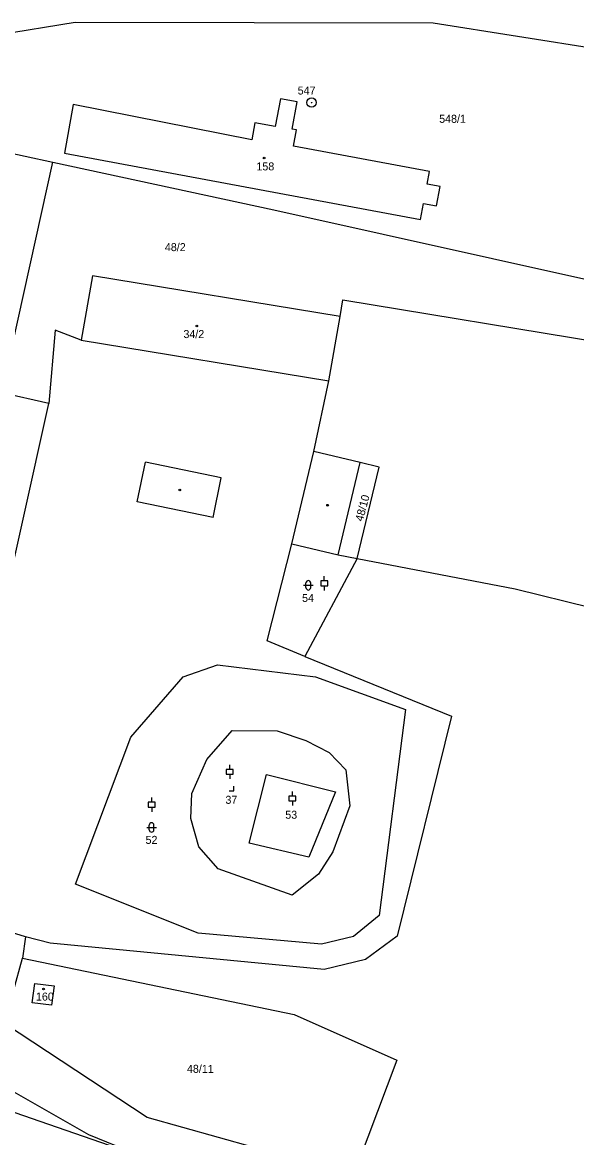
# Model space of a CAD drawing. Extents: x -801826 to -800592, y -1032871 to -1031813.
# Drawn here: x -801242.3 to -801124.4, y -1032295.9 to -1032058.9 of the extents above; entities that cross this region are included whole.
import ezdxf

# ---------------------------------------------------------------- set-up
doc = ezdxf.new("R2010")
doc.units = 0
for name, color, linetype in [('Vrstva 1', 7, 'Continuous'), ('Vrstva 17', 7, 'Continuous'), ('Vrstva 18', 7, 'Continuous'), ('Vrstva 19', 7, 'Continuous'), ('Vrstva 24', 7, 'Continuous'), ('Vrstva 25', 7, 'Continuous'), ('Vrstva 4', 7, 'Continuous')]:
    doc.layers.add(name, color=color, linetype=linetype)

msp = doc.modelspace()

# ---------------------------------------------------------------- linework, layer by layer
at = {"layer": 'Vrstva 1'}
for p, q in [((-801262.98, -1032064), (-801231.11, -1032058.94)), ((-801231.11, -1032058.94), (-801155, -1032059.05)), ((-801155, -1032059.05), (-801101, -1032067.63)), ((-801231.51, -1032076.39), (-801233.35, -1032086.76)), ((-801193.55, -1032083.9), (-801231.51, -1032076.39)), ((-801187.45, -1032075.17), (-801188.55, -1032081.07)), ((-801183.86, -1032075.84), (-801187.45, -1032075.17)), ((-801184.94, -1032081.64), (-801183.86, -1032075.84)), ((-801192.87, -1032080.26), (-801193.55, -1032083.9)), ((-801188.55, -1032081.07), (-801192.87, -1032080.26)), ((-801258.71, -1032083.73), (-801235.82, -1032088.67)), ((-801184.01, -1032081.81), (-801184.94, -1032081.64)), ((-801184.65, -1032085.25), (-801184.01, -1032081.81)), ((-801155.75, -1032090.64), (-801184.65, -1032085.25)), ((-801245.62, -1032132.9), (-801235.82, -1032088.67)), ((-801235.82, -1032088.67), (-801188.88, -1032098.79)), ((-801233.35, -1032086.76), (-801157.65, -1032100.86)), ((-801156.24, -1032093.29), (-801155.75, -1032090.64)), ((-801153.49, -1032093.8), (-801156.24, -1032093.29)), ((-801154.26, -1032097.93), (-801153.49, -1032093.8)), ((-801157.65, -1032100.86), (-801157.01, -1032097.42)), ((-801157.01, -1032097.42), (-801154.26, -1032097.93)), ((-801188.88, -1032098.79), (-801114.92, -1032115.22)), ((-801227.44, -1032112.79), (-801229.85, -1032126.45)), ((-801174.76, -1032121.41), (-801227.44, -1032112.79)), ((-801174.76, -1032121.41), (-801174.17, -1032117.88)), ((-801174.17, -1032117.88), (-801118.72, -1032127.06)), ((-801177.15, -1032135.08), (-801174.76, -1032121.41)), ((-801235.38, -1032124.35), (-801236.7, -1032139.95)), ((-801229.85, -1032126.45), (-801235.38, -1032124.35)), ((-801229.85, -1032126.45), (-801177.15, -1032135.08)), ((-801180.36, -1032150.13), (-801177.15, -1032135.08)), ((-801236.7, -1032139.95), (-801246.67, -1032137.64)), ((-801170.51, -1032152.42), (-801180.36, -1032150.13)), ((-801175.17, -1032172.07), (-801170.51, -1032152.42)), ((-801166.45, -1032153.44), (-801170.51, -1032152.42)), ((-801171.1, -1032172.83), (-801166.45, -1032153.44)), ((-801190.26, -1032190.37), (-801185.04, -1032169.71)), ((-801185.04, -1032169.71), (-801175.17, -1032172.07)), ((-801171.1, -1032172.83), (-801182.26, -1032193.66)), ((-801175.17, -1032172.07), (-801171.1, -1032172.83)), ((-801171.1, -1032172.83), (-801137.55, -1032179.29)), ((-801137.55, -1032179.29), (-801121.44, -1032183.28)), ((-801182.26, -1032193.66), (-801190.26, -1032190.37)), ((-801182.26, -1032193.66), (-801151.09, -1032206.33)), ((-801208.1, -1032197.96), (-801200.82, -1032195.46)), ((-801200.82, -1032195.46), (-801180, -1032197.96)), ((-801219.29, -1032210.8), (-801208.1, -1032197.96)), ((-801180, -1032197.96), (-801160.86, -1032204.93)), ((-801160.86, -1032204.93), (-801166.44, -1032248.68)), ((-801151.09, -1032206.33), (-801162.63, -1032253.04)), ((-801203.12, -1032215.52), (-801197.7, -1032209.41)), ((-801197.7, -1032209.41), (-801188.12, -1032209.45)), ((-801188.12, -1032209.45), (-801182.05, -1032211.53)), ((-801231.06, -1032242.05), (-801219.29, -1032210.8)), ((-801182.05, -1032211.53), (-801177.08, -1032214.05)), ((-801177.08, -1032214.05), (-801173.53, -1032217.76)), ((-801206.3, -1032222.74), (-801203.12, -1032215.52)), ((-801194.07, -1032233.33), (-801190.44, -1032218.75)), ((-801190.44, -1032218.75), (-801175.71, -1032222.38)), ((-801173.53, -1032217.76), (-801172.72, -1032225.39)), ((-801206.5, -1032228.08), (-801206.3, -1032222.74)), ((-801175.71, -1032222.38), (-801181.43, -1032236.27)), ((-801172.72, -1032225.39), (-801176.34, -1032235.17)), ((-801204.79, -1032234.11), (-801206.5, -1032228.08)), ((-801200.67, -1032238.8), (-801204.79, -1032234.11)), ((-801181.43, -1032236.27), (-801194.07, -1032233.33)), ((-801176.34, -1032235.17), (-801179.36, -1032239.9)), ((-801184.94, -1032244.39), (-801200.67, -1032238.8)), ((-801179.36, -1032239.9), (-801184.94, -1032244.39)), ((-801204.96, -1032252.47), (-801231.06, -1032242.05)), ((-801166.44, -1032248.68), (-801171.94, -1032253.12)), ((-801241.66, -1032253.23), (-801246.69, -1032251.67)), ((-801241.66, -1032253.23), (-801242.31, -1032257.72)), ((-801236.4, -1032254.58), (-801241.66, -1032253.23)), ((-801178.71, -1032254.75), (-801204.96, -1032252.47)), ((-801171.94, -1032253.12), (-801178.71, -1032254.75)), ((-801162.63, -1032253.04), (-801169.36, -1032258.05)), ((-801178.12, -1032260.13), (-801236.4, -1032254.58)), ((-801246.16, -1032271.65), (-801242.31, -1032257.72)), ((-801242.31, -1032257.72), (-801184.54, -1032269.72)), ((-801169.36, -1032258.05), (-801178.12, -1032260.13)), ((-801240.22, -1032267.23), (-801239.7, -1032263.13)), ((-801239.7, -1032263.13), (-801235.6, -1032263.65)), ((-801235.6, -1032263.65), (-801236.12, -1032267.75)), ((-801236.12, -1032267.75), (-801240.22, -1032267.23)), ((-801184.54, -1032269.72), (-801162.68, -1032279.42)), ((-801215.82, -1032291.6), (-801246.16, -1032271.65)), ((-801162.68, -1032279.42), (-801172.28, -1032304.86)), ((-801228.18, -1032295.28), (-801246.04, -1032285.11)), ((-801253.19, -1032287.31), (-801216.74, -1032299.98)), ((-801185.47, -1032300.06), (-801215.82, -1032291.6)), ((-801216.74, -1032299.98), (-801228.18, -1032295.28))]:
    msp.add_line(p, q, dxfattribs=at)
at = {"layer": 'Vrstva 24'}
for radius in [1, 0.0439]:
    msp.add_circle((-801180.84, -1032076), radius, dxfattribs=at)
at = {"layer": 'Vrstva 25'}
for p, q in [((-801182.52, -1032178.54), (-801180.52, -1032178.54)), ((-801182.02, -1032179.04), (-801182.02, -1032178.04)), ((-801181.02, -1032179.04), (-801181.02, -1032178.04)), ((-801178.14, -1032177.62), (-801178.14, -1032176.62)), ((-801178.14, -1032178.62), (-801178.14, -1032179.62)), ((-801198.24, -1032217.65), (-801198.24, -1032216.65)), ((-801198.24, -1032218.65), (-801198.24, -1032219.65)), ((-801197.33, -1032222.22), (-801197.33, -1032221.22)), ((-801214.83, -1032224.64), (-801214.83, -1032223.64)), ((-801198.33, -1032222.22), (-801197.33, -1032222.22)), ((-801184.91, -1032223.33), (-801184.91, -1032222.33)), ((-801214.83, -1032225.64), (-801214.83, -1032226.64)), ((-801184.91, -1032224.33), (-801184.91, -1032225.33)), ((-801215.84, -1032229.98), (-801213.84, -1032229.98)), ((-801215.34, -1032230.48), (-801215.34, -1032229.48)), ((-801214.34, -1032230.48), (-801214.34, -1032229.48))]:
    msp.add_line(p, q, dxfattribs=at)
for points in [[(-801178.89, -1032178.62), (-801177.39, -1032178.62), (-801177.39, -1032177.62), (-801178.89, -1032177.62)], [(-801198.99, -1032218.65), (-801197.49, -1032218.65), (-801197.49, -1032217.65), (-801198.99, -1032217.65)], [(-801185.66, -1032224.33), (-801184.16, -1032224.33), (-801184.16, -1032223.33), (-801185.66, -1032223.33)], [(-801215.58, -1032225.64), (-801214.08, -1032225.64), (-801214.08, -1032224.64), (-801215.58, -1032224.64)]]:
    msp.add_lwpolyline(points, close=True, dxfattribs=at)
for centre in [(-801190.92, -1032087.77), (-801205.23, -1032123.47), (-801208.86, -1032158.28), (-801177.43, -1032161.52), (-801237.82, -1032264.31)]:
    msp.add_circle(centre, 0.175, dxfattribs=at)
for centre, start, end in [((-801181.52, -1032178.04), 0, 180), ((-801181.52, -1032179.04), 180, 0), ((-801214.84, -1032229.48), 0, 180), ((-801214.84, -1032230.48), 180, 0)]:
    msp.add_arc(centre, 0.5, start, end, dxfattribs=at)
at = {"layer": 'Vrstva 4'}
for p, q in [((-801251.33, -1032205.54), (-801236.7, -1032139.95)), ((-801185.04, -1032169.71), (-801180.36, -1032150.13)), ((-801217.92, -1032160.79), (-801216.16, -1032152.37)), ((-801200.02, -1032155.74), (-801216.16, -1032152.37)), ((-801201.78, -1032164.16), (-801200.02, -1032155.74)), ((-801201.78, -1032164.16), (-801217.92, -1032160.79))]:
    msp.add_line(p, q, dxfattribs=at)

# ---------------------------------------------------------------- texts
at = {"layer": 'Vrstva 17'}
msp.add_text('547', height=1.7, dxfattribs=at).set_placement((-801183.78, -1032074.28))
at = {"layer": 'Vrstva 18'}
for s, p in [('548/1', (-801153.7, -1032080.29)), ('48/2', (-801212.02, -1032107.55)), ('54', (-801182.85, -1032182.08)), ('53', (-801186.42, -1032228.13)), ('52', (-801216.13, -1032233.47)), ('48/11', (-801207.33, -1032282.11))]:
    msp.add_text(s, height=1.7, dxfattribs=at).set_placement(p)
msp.add_text('48/10', height=1.7, rotation=74.8459, dxfattribs=at).set_placement((-801169.95, -1032165.08))
at = {"layer": 'Vrstva 19'}
for s, p in [('158', (-801192.56, -1032090.4)), ('34/2', (-801208.08, -1032126.02)), ('37', (-801199.15, -1032224.96)), ('160', (-801239.44, -1032266.76))]:
    msp.add_text(s, height=1.7, dxfattribs=at).set_placement(p)

doc.saveas('drawing.dxf')
